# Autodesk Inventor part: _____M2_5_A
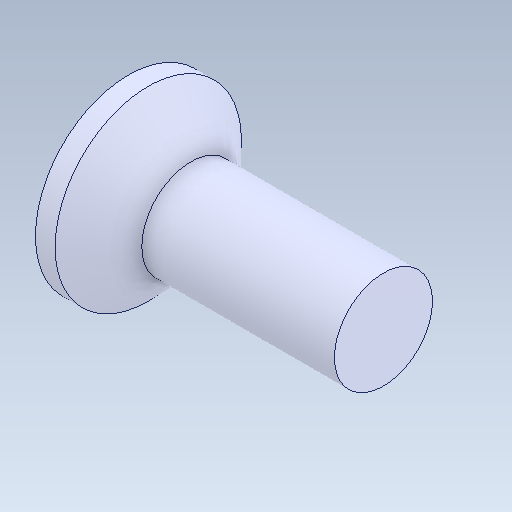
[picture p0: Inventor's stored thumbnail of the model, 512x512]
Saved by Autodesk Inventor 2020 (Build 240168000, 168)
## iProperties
Created: 2017-09
Part Number: _____M2_5_A
Material: Générique
Document SubType Name: Modeling
Designer: bruno
Density: 1 g/cm^3
Appearance: Par défaut
Author: bruno
Sending System: SolidWorks 2016
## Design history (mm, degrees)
feature "Importée1"
node "Solide1"
